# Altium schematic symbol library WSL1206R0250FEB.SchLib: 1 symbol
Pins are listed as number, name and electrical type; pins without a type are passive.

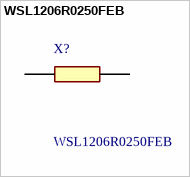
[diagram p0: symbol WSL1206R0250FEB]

## WSL1206R0250FEB
designator X?
Current Sense Resistors - SMD 1/4watt .025ohms 1%; Manufacturer_Name: Vishay; Geometry.Height: 0.889mm
footprint RESC3216X89N
pins: 1, 2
